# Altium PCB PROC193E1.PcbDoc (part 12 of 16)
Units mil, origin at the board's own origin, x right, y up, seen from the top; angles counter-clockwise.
Board outline 7700 x 2300 mil, 6 copper layers (Top Layer, GND 1, SIG 1, PWR, GND 2, Bottom Layer), stack 60.98 mil thick; 946 components, 667 nets, 9401 pads, 1730 vias.
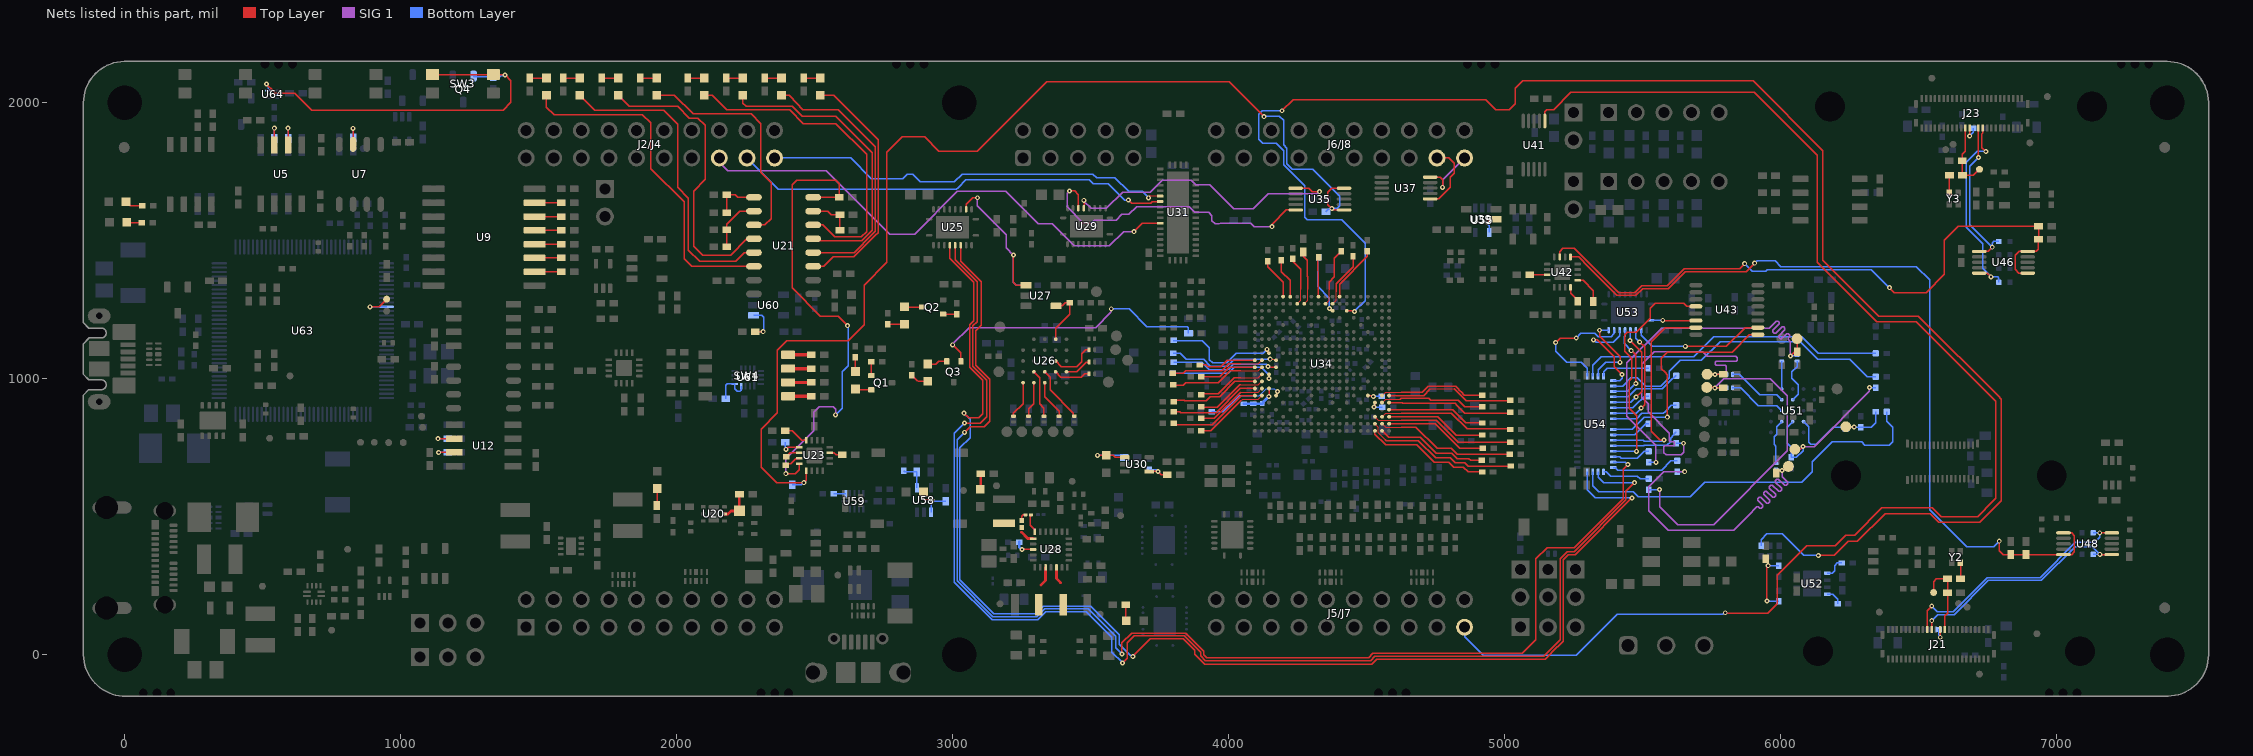
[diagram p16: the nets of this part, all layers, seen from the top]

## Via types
v1: diameter 18, hole 8, Top Layer to Bottom Layer, tented both sides, 1710 vias
v2: diameter 18, hole 8, Top Layer to Bottom Layer, tented top, 12 vias
v3: diameter 23.62, hole 11.81, Top Layer to Bottom Layer, tented both sides, 8 vias

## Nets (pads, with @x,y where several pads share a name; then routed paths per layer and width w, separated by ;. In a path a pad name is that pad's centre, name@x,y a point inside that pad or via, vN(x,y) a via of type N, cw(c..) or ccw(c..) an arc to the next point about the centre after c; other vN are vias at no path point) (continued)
I2C1_SDA/GPIO136: J5/J7.50 U41.6 | length 5047.8
  Top Layer w5.3: U41.6@5145.29,1934.2 5145.29,1967.62 5152.68,1975.01 5176.73,1975.01 5239.85,2038.13 5903.11,2038.13 6131.62,1809.62 6131.62,1422.45 6347.18,1206.9 6490.27,1206.9 6778.91,918.26 6778.91,566.97 6767.79,555.85 6712.73,500.78 6580.92,500.78 6549.26,532.44 6536.12,532.44 6366.44,532.44 6267.06,433.06 6235.77,433.06 6198.08,395.37 6094.25,395.37 6088.32,389.44 5986.96,288.08 5986.96,184.37 5953.38,150.79 5800.23,150.79 v1(5798.69,152.33)
  Bottom Layer w5.3: J5/J7.50@4854.17,100 4855.77,98.4 4855.77,64.64 4921.15,-0.73 5259.43,-0.73 5395.83,135.67 5396.03,135.67 5406.57,146.21 5789.23,146.21 5795.36,152.33 v1(5798.69,152.33)
I2C_EX1_ADDR: R188.2 U42.16 | length 60.2
  Top Layer w5.3: U42.16@5238.05,1331.1 5238.05,1310.38 5263.64,1284.79 R188.2@5263.64,1281.48
I2C_EX1_INTN: R184.2 U42.11 | length 62.6
  Top Layer w5.3: R184.2@5090.84,1376.37 U42.11@5153.4,1376.37
I2C_EX1_RSTN: R191.2 U42.1 | length 111.8
  Top Layer w5.3: U42.1@5263.64,1356.69 5283.4,1356.69 5321.3,1318.78 R191.2@5321.3,1280.35
I2C_EX2_ADDR: R63.1 U23.16 | length 90.5
  Top Layer w5.3: R63.1@2392.66,811.04 2418.1,811.04 2451.88,777.27 U23.16@2469.17,777.27
I2C_EX2_INTN: R77.2 U23.11 | length 48.9
  Top Layer w5.3: U23.11@2553.81,731.99 2554.09,731.71 2569.55,731.71 2576.99,724.27 R77.2@2599.51,724.27
I2C_EX2_RSTN: R364.2 U23.1 | length 77.9
  Top Layer w5.3: v1(2395.21,744.52) 2397.51,744.52 2404.66,751.68 U23.1@2443.57,751.68
  Bottom Layer w5.3: R364.2@2392.66,770 2392.66,747.07 v1(2395.21,744.52)
ICSS1_INH: J21.26 R239.2 | length 58.8
  Top Layer w5.3: v1(6577.74,63.37) 6578.04,63.66 J21.26@6578.04,91.39
  Bottom Layer w5.3: R239.2@6572.06,91.67 6572.06,72.49 6577.74,66.81 v1(6577.74,63.37)
ICSS2_INH: J23.26 R233.2 | length 62.3
  Top Layer w5.3: v1(6684.43,1879.92) J23.26@6684.43,1908.44
  Bottom Layer w5.3: v1(6684.43,1879.92) 6697.48,1892.97 R233.2@6697.48,1908.33
INT1_PB: Q4.2 R378.1 SW3.2 SW3.4 U64.3 | length 1453.2
  Top Layer w5.3: v1(513.14,2068) 540.03,2041.1 545.91,2035.23 615.14,2035.23 677.45,1972.91 1219.96,1972.91 1235.6,1972.91 1370.64,1972.91 1399.03,2001.3 1399.03,2079.77 v1(1377.8,2101) 1336.52,2101 SW3.4@1335.24,2102.28 SW3.2@1114.76,2102.28
  Bottom Layer w5.3: v1(513.14,2068) 519.68,2061.46 U64.3@519.68,2043.98 ; Q4.2@1263.53,2096.74 1265.15,2095.12 R378.1@1335.24,2095.12 1358.2,2095.12 1361.65,2098.57 1375.37,2098.57 v1(1377.8,2101)
LED_A0: R55.2 R56.2 U21.9 | length 166.8
  Top Layer w5.3: R55.2@2181.39,1602.28 R56.2@2181.39,1666.96 2211.84,1666.96 2221.37,1657.42 U21.9@2279.55,1657.42
LED_A1: R53.2 R54.2 U21.10 | length 198.7
  Top Layer w5.3: R53.2@2181.39,1478.99 R54.2@2181.39,1539.3 2181.39,1559.83 2228.98,1607.42 U21.10@2279.55,1607.42
LED_A2: R75.2 R76.2 U21.7 | length 157.7
  Top Layer w5.3: U21.7@2494.12,1607.42 2546.84,1607.42 2560.28,1593.98 R76.2@2591.22,1593.98 R75.2@2591.22,1538.98
LED_ANODE0: D11.2 R67.1 | length 60
  Top Layer w5.3: R67.1@2459.29,2089.8 D11.2@2519.29,2089.8
LED_ANODE1: D10.2 R62.1 | length 60
  Top Layer w5.3: R62.1@2319.29,2089.8 D10.2@2379.29,2089.8
LED_ANODE2: D9.2 R58.1 | length 60
  Top Layer w5.3: R58.1@2179.29,2089.8 D9.2@2239.29,2089.8
LED_ANODE3: D8.2 R52.1 | length 60
  Top Layer w5.3: R52.1@2039.29,2089.8 D8.2@2099.29,2089.8
LED_ANODE4: D6.2 R42.1 | length 60
  Top Layer w5.3: R42.1@1867.87,2089.8 D6.2@1927.87,2089.8
LED_ANODE5: D5.2 R41.1 | length 60
  Top Layer w5.3: R41.1@1727.87,2089.8 D5.2@1787.87,2089.8
LED_ANODE6: D4.2 R38.1 | length 60
  Top Layer w5.3: R38.1@1587.87,2089.8 D4.2@1647.87,2089.8
LED_ANODE7: D3.2 R26.1 | length 60
  Top Layer w5.3: R26.1@1467.87,2089.8 D3.2@1527.87,2089.8
LED_DRAIN0: D11.1 U21.3 | length 898.8
  Top Layer w5.3: U21.3@2494.12,1407.42 2532.47,1407.42 2566.86,1441.82 2641.63,1441.82 2719.59,1519.78 2729.32,1529.5 2729.32,1548.83 2729.32,1805.31 2729.32,1811.99 2729.32,1819.74 2729.32,1834.05 2729.32,1865.9 2568.4,2026.81 D11.1@2519.29,2026.81
LED_DRAIN1: D10.1 U21.4 | length 981
  Top Layer w5.3: D10.1@2379.29,2026.81 2407.66,2026.81 2410.77,2023.71 2456.86,1974.27 2585.73,1974.27 2718.72,1841.29 2718.72,1553.22 2718.72,1533.89 2708.99,1524.17 2642.25,1457.42 U21.4@2494.12,1457.42
LED_DRAIN2: D9.1 U21.5 | length 1085.8
  Top Layer w5.3: D9.1@2239.29,2026.81 2239.29,1998.55 2251.11,1986.73 2418.49,1986.73 2453.8,1951.42 2576.58,1951.42 2708.11,1819.89 2708.11,1557.62 2708.11,1538.28 2669.59,1499.76 2501.78,1499.76 U21.5@2494.12,1507.42
LED_DRAIN3: D8.1 U21.6 | length 1176.9
  Top Layer w5.3: D8.1@2099.29,2026.81 2129.12,2026.81 2181.66,1974.27 2408.67,1974.27 2458.21,1924.73 2576.27,1924.73 2687.79,1813.21 2687.79,1602.13 2687.79,1585.95 2687.79,1532.95 2668.7,1513.86 2572.48,1513.86 2528.92,1557.42 U21.6@2494.12,1557.42
LED_DRAIN4: D6.1 U21.11 | length 850.9
  Top Layer w5.3: D6.1@1927.87,2026.81 1991.48,2026.81 2058.87,1959.42 2269.55,1959.42 2304.25,1924.73 2304.25,1748.99 2342.2,1711.03 2342.2,1580.33 2319.29,1557.42 U21.11@2279.55,1557.42
LED_DRAIN5: D5.1 U21.12 | length 1072
  Top Layer w5.3: D5.1@1787.87,2026.81 1827.95,1986.73 2003.75,1986.73 2045.7,1944.78 2076.59,1944.78 2103.23,1918.14 2103.23,1722.11 2061.23,1680.11 2061.23,1480.09 2093.24,1448.08 2194.74,1448.08 2254.08,1507.42 U21.12@2279.55,1507.42
LED_DRAIN6: D4.1 U21.13 | length 1138.5
  Top Layer w5.3: D4.1@1647.87,2026.81 1702.19,1972.5 1953.33,1972.5 2003.75,1922.08 2003.75,1693.24 2042.23,1654.76 2042.23,1466.03 2082.64,1425.62 2212.84,1425.62 2244.64,1457.42 U21.13@2279.55,1457.42
LED_DRAIN7: D3.1 U21.14 | length 1250.8
  Top Layer w5.3: D3.1@1527.87,2026.81 1527.87,1984.63 1555.24,1957.27 1875.6,1957.27 1906,1926.87 1906,1761.39 2026.48,1640.91 2026.48,1434.43 2053.49,1407.42 U21.14@2279.55,1407.42
LED_DRIVER_EN: R74.2 U21.8 U23.4 | length 1749.9
  Top Layer w5.3: v1(2395.05,656.33) 2428.94,656.33 2443.57,670.97 U23.4@2443.57,692.62 ; U21.8@2494.12,1657.42 R74.2@2588.21,1657.42 2588.21,1706.9 2575.47,1719.64 2433.89,1719.64 2418.09,1703.84 2418.09,1329.43 2520.44,1227.09 2584.11,1227.09 v1(2618.69,1192.5)
  SIG 1 w5.3: v1(2395.05,656.33) 2395.05,710.02 2496.99,811.96 2496.99,877.99 2516.93,897.93 2567.07,897.93 2575.47,889.53 v1(2575.47,869.52)
  Bottom Layer w5.3: v1(2575.47,869.52) 2600.11,894.16 2600.11,1026.72 2603.43,1030.04 2609.46,1036.07 2609.46,1036.15 2620.4,1047.08 2620.4,1190.79 v1(2618.69,1192.5)
LIN1_RXD/PR1_PRU1_GPIO0: J2/J4.33 U31.11 | length 1899.9
  Top Layer w5.3: v1(3656,1533) 3686.61,1563.61 U31.11@3751.12,1563.61
  SIG 1 w4.75: J2/J4.33@2154.17,1800 2154.17,1785.28 2185.12,1754.33 2541.05,1754.33 2771.05,1524.33 2861.86,1524.33 3016.69,1679.16 3192.46,1679.16 3309.79,1561.84 3359.71,1561.84 3440.17,1481.38 3567.23,1481.38 3618.85,1533 v1(3656,1533)
M_EQEP0_A: U43.6 U53.1 | length 162.4
  Top Layer w5.3: v1(5572.32,1211.87) 5573.09,1211.11 5603.41,1211.11 5652.29,1211.11 U43.6@5692.24,1211.11
  Bottom Layer w5.3: U53.1@5530.13,1211.87 v1(5572.32,1211.87)
M_EQEP0_B: U43.10 U53.3 | length 485.6
  Top Layer w5.3: v1(5654.03,1117.71) 5802.93,1117.71 5870.74,1185.52 U43.10@5916.65,1185.52
  Bottom Layer w5.3: U53.3@5494.7,1176.44 5494.7,1157.3 5534.28,1117.71 v1(5654.03,1117.71)
M_EQEP0_INDEX: U53.4 U54.28 | length 409.1
  Top Layer w5.3: v1(5488.74,1133) 5506.27,1115.47 5506.27,1101.02 ; v1(5494.06,894.07) 5506.27,906.28 5506.27,942.93 ; 5506.28,942.94 5506.28,977.4 5506.28,1101.01
  Bottom Layer w5.3: U54.28@5393.04,875.4 5475.39,875.4 v1(5494.06,894.07) ; U53.4@5475.01,1176.44 5475.01,1146.73 v1(5488.74,1133)
M_EQEP0_STROBE: U53.5 U54.26 | length 359.6
  Top Layer w5.3: v1(5453.42,1138.88) 5495.68,1096.62 5495.68,953.98 v1(5476.16,934.46)
  Bottom Layer w5.3: U54.26@5393.04,914.77 5456.48,914.77 v1(5476.16,934.46) ; v1(5453.42,1138.88) 5455.33,1140.79 U53.5@5455.33,1176.44
M_EQEP1_A: U53.6 U54.24 | length 306.9
  Top Layer w5.3: v1(5458,1102) 5459.31,1102 5474.54,1086.78 v1(5474.54,982.98)
  Bottom Layer w5.3: U54.24@5393.04,954.14 5445.69,954.14 v1(5474.54,982.98) ; U53.6@5435.64,1176.44 5435.64,1156.68 5431.88,1152.92 5431.88,1128.12 v1(5458,1102)
M_EQEP1_B: U53.7 U54.22 | length 352.9
  Top Layer w5.3: v1(5321.75,1141.1) 5335.73,1141.1 5396.27,1080.56 5396.27,1043.54 v1(5424.23,1015.58)
  Bottom Layer w5.3: v1(5321.75,1141.1) 5323.07,1141.1 5331.21,1132.97 5392.25,1132.97 5415.96,1156.68 U53.7@5415.96,1176.44 ; U54.22@5393.04,993.51 5416.87,993.51 5425,1001.64 5425,1014.81 v1(5424.23,1015.58)
M_EQEP1_INDEX: U53.8 U54.18 | length 448
  Top Layer w5.3: v1(5184.36,1131.22) 5200.79,1147.65 v1(5258.87,1147.65)
  Bottom Layer w5.3: v1(5184.36,1131.22) 5184.22,1131.07 5184.22,1099.61 5223.62,1060.21 5276.26,1060.21 5298.55,1037.92 U54.18@5298.55,1009.26 ; v1(5258.87,1147.65) 5276.01,1164.78 5326.2,1164.78 5338.03,1152.95 5385.26,1152.95 5395.48,1163.17 5395.48,1175.65 U53.8@5396.27,1176.44
M_EQEP1_STROBE: U53.9 U54.20 | length 294.3
  Top Layer w5.3: v1(5343.46,1175.91) 5343.46,1153.43 5417.64,1079.24 v1(5417.64,1059.69)
  Bottom Layer w5.3: U54.20@5337.92,1009.26 5337.92,1032.14 5365.47,1059.69 v1(5417.64,1059.69) ; v1(5343.46,1175.91) 5343.73,1176.17 5376.32,1176.17 U53.9@5376.59,1176.44
M_FSIRX0_CLK: U43.4 U54.35 | length 862.9
  Top Layer w5.3: v1(5477.58,737.18) 5477.58,866.42 5451.52,892.48 5451.52,992.96 5460.66,1002.1 5460.66,1073.04 5450.35,1083.35 5450.27,1083.35 5439.35,1094.28 5439.35,1094.35 5434.09,1099.61 5434.09,1159.32 5443.26,1168.48 5475.67,1168.48 5527.45,1220.26 5527.45,1255.75 5544.66,1272.96 5648.16,1272.96 5658.83,1262.29 U43.4@5692.24,1262.29
  Bottom Layer w5.3: U54.35@5393.04,737.61 5477.15,737.61 v1(5477.58,737.18)
M_FSIRX0_DATA0/EQEP0_A: U43.7 U54.33 | length 752.1
  Top Layer w5.3: v1(5576.67,777.97) 5576.53,778.11 5563.44,778.11 5530.99,810.56 5530.99,1134.4 5582.12,1185.52 U43.7@5692.24,1185.52
  Bottom Layer w5.3: U54.33@5393.04,776.98 5501.34,776.98 5504.47,773.85 5569.11,773.85 5573.24,777.97 v1(5576.67,777.97)
M_FSIRX0_DATA1/EQEP0_B: U43.9 U54.31 | length 822.4
  Top Layer w5.3: v1(5588.66,860.76) 5588.66,1015.25 5580.86,1023.05 5580.66,1023.05 5566.83,1036.88 5566.83,1074.91 5588.91,1097 5823.66,1097 5886.59,1159.93 U43.9@5916.65,1159.93
  Bottom Layer w5.3: U54.31@5393.04,816.35 5461.28,816.35 5505.69,860.76 v1(5588.66,860.76)
M_FSITX0_CLK: U25.5 U54.42 | length 4707.3
  Top Layer w5.3: U25.5@2989.13,1484.11 2989.13,1435.88 3075.76,1349.24 3075.76,1210.01 3061.46,1195.7 3061.46,1041.2 3108.47,994.19 3108.47,873.06 3094.09,858.68 3057.22,858.68 v1(3040.35,875.54) ; v1(3652.17,-5.73) 3715.84,57.94 3834.67,57.94 3876.54,16.07 3876.54,2.12 3912.04,-33.39 4518.61,-33.39 4536.26,-15.74 5146.04,-15.74 5190.83,29.05 5191.04,29.05 5211.87,49.88 5211.87,344.39 5230.79,363.32 5255.13,363.32 v1(5460.35,568.53)
  Bottom Layer w5.3: v1(3040.35,875.54) 3062.6,853.29 3062.6,786.29 3025.8,749.49 3025.8,271.84 3148.94,148.7 3149.72,147.92 3150.83,147.92 3299.72,147.92 3328.54,176.75 3499.05,176.75 3603.66,72.14 3603.66,38.71 3643.45,-1.08 3644.09,-1.08 3648.74,-5.73 v1(3652.17,-5.73) ; U54.42@5298.55,662.8 5298.55,598.52 5328.54,568.53 v1(5460.35,568.53)
M_FSITX0_DATA0: U25.6 U54.40 | length 4737.9
  Top Layer w5.3: U25.6@3008.81,1484.11 3008.81,1431.19 3087.68,1352.32 3087.68,1206.93 3072.06,1191.31 3072.06,1045.59 3122.46,995.18 3122.46,862.98 3098.85,839.37 v1(3042.19,839.37) ; v1@3615.26,-29.15 3631.97,-12.44 3631.97,42.77 3657.44,68.24 3838.93,68.24 3898.37,8.81 3898.37,-3.75 3915.42,-20.8 4513.57,-20.8 4528.93,-5.44 5141.77,-5.44 5186.56,39.35 5186.77,39.35 5201.57,54.14 5201.57,348.66 5226.53,373.61 5250.87,373.61 5439,561.75 5439,593.09 v1(5469.57,623.65)
  Bottom Layer w5.3: v1(3042.19,839.37) 3004.97,802.14 3004.97,263.54 3140.41,128.1 3141.32,127.19 3142.43,127.19 3308.12,127.19 3337.07,156.15 3484.23,156.15 3576.01,64.37 3576.01,9.83 v1(3615.13,-29.28) ; U54.40@5337.92,662.8 5337.92,643.82 5350.21,631.54 5358.09,623.65 v1(5469.57,623.65)
M_FSITX0_DATA1: U25.7 U54.37 | length 4624.1
  Top Layer w5.3: U25.7@3028.5,1484.11 3028.5,1426.49 3102.68,1352.32 3102.68,1193.93 3082.66,1173.91 3082.66,1049.98 3134.62,998.02 3134.62,846.84 3114.28,826.5 3062.97,826.5 v1(3042.46,805.99) ; v1(3613,3) 3613,42.91 3648.63,78.54 3843.2,78.54 3908.67,13.07 3908.67,0.51 3919.59,-10.41 4506.32,-10.41 4521.59,4.86 5063.75,4.86 5112.72,53.82 5112.72,348.07 5153.19,388.54 5251.23,388.54 5428.45,565.76 5428.45,671.9 v1(5445.58,689.03)
  Bottom Layer w5.3: v1(3042.46,805.99) 3015.27,778.8 3015.27,267.81 3144.68,138.4 3145.58,137.49 3146.7,137.49 3303.85,137.49 3332.81,166.45 3491.06,166.45 3591.05,66.46 3591.05,24.95 v1(3613,3) ; U54.37@5393.04,698.23 5436.12,698.23 5445.33,689.03 v1(5445.58,689.03)
M_OSPI1_CLK: R242.1 R245.1 U54.41 | length 1383.5
  Bottom Layer w5.3: U54.41@5318.24,662.8 5318.24,612.8 5340.05,590.99 5465.5,590.99 5483.01,573.48 5671.74,573.48 5723.56,625.31 6076.31,625.31 6113.45,662.45 6113.45,698.63 6186.47,771.64 6293.36,771.64 6305,760 6393.17,760 6405,771.83 6405,824.18 6383.34,845.84 6383.34,880.25 R242.1@6383.42,880.32
M_OSPI1_CSN0: R243.1 R248.1 U54.23 | length 1107.9
  Bottom Layer w5.3: U54.23@5393.04,973.83 5427.38,973.83 5456.76,1003.2 5480.69,1003.2 5493.19,990.71 5493.19,990.63 5509.99,973.83 5565.69,973.83 5596.28,1004.42 5596.28,1026.91 5636.37,1067 5712,1067 5780,1135 6070.43,1135 6133.77,1071.66 6249.34,1071.66 6313.74,1007.26 R248.1@6343.71,1007.26
M_OSPI1_D0: R286.1 R291.1 U54.39 | length 173.8
  Bottom Layer w5.3: U54.39@5357.61,662.8 5368.25,662.8 5383.78,647.27 5480.73,647.27 5489.89,638.11 R291.1@5521.14,638.11
M_OSPI1_D1: R276.1 R282.1 U54.38 | length 250.5
  Bottom Layer w5.3: U54.38@5393.04,678.55 5399.93,678.55 5410.01,668.47 5567.94,668.47 5602.05,702.58 R282.1@5625.21,702.58
M_OSPI1_D2: R289.1 R294.1 U54.36 | length 140.9
  Bottom Layer w5.3: U54.36@5393.04,717.92 5416.34,717.92 5422.58,711.68 5479.7,711.68 5504.67,736.65 R294.1@5520.97,736.65
M_OSPI1_D3: R277.1 R283.1 U54.34 | length 257.7
  Bottom Layer w5.3: U54.34@5393.04,757.29 5502.82,757.29 5504.52,758.99 5535.17,758.99 5535.71,758.45 5587.42,758.45 5600.91,771.93 5600.91,785.32 5612.11,796.53 5612.11,798.5 5619.3,805.69 R283.1@5621.27,805.69
M_OSPI1_D4: R287.1 R292.1 U54.32 | length 145
  Bottom Layer w5.3: U54.32@5393.04,796.66 5470.71,796.66 5472.34,798.29 5511.44,837.39 R292.1@5521.14,837.39
M_OSPI1_D5: R278.1 R284.1 U54.29 | length 248.2
  Bottom Layer w5.3: U54.29@5393.04,855.72 5460.66,855.72 5477.69,855.72 5496.36,874.39 5574.43,874.39 5581.02,880.98 5603.95,903.91 R284.1@5621.27,903.91
M_OSPI1_D6: R290.1 R295.1 U54.27 | length 145.5
  Bottom Layer w5.3: U54.27@5393.04,895.09 5464.4,895.09 5484.25,914.93 5495.69,926.37 5506.73,937.41 R295.1@5520.97,937.41
M_OSPI1_D7: R279.1 R285.1 U54.25 | length 260.2
  Bottom Layer w5.3: U54.25@5393.04,934.46 5447.39,934.46 5476.16,963.23 5570.08,963.23 5573.59,966.74 5573.76,966.74 5598.35,991.33 5618.64,1011.62 R285.1@5621.27,1011.62
M_OSPI1_DQS: R288.1 R293.1 U54.21 | length 184.4
  Bottom Layer w5.3: U54.21@5357.61,1009.26 5358.24,1009.89 5358.24,1024.85 5371.96,1038.57 R293.1@5521.14,1038.57
M_OSPI1_ECC_FAIL: R244.1 R249.1 U54.19 | length 1132.5
  Bottom Layer w5.3: U54.19@5318.24,1009.26 5318.24,1048.44 5349.74,1079.95 5684.52,1079.95 5756.58,1152 6075.44,1152 6135.62,1091.82 6343.65,1091.82 R249.1@6343.71,1091.76
MCAN0_RX: U29.17 U35.10 | length 1100.3
  Top Layer w5.3: v1(3422.56,1680.77) 3442.17,1680.77 3455.31,1667.64 3455.31,1651.47 3455.13,1651.29 U29.17@3455.13,1618.16 ; v1(4156.69,1551.25) 4156.69,1560.83 4207.5,1611.64 U35.10@4242.38,1611.64
  SIG 1 w4.75: v1(3422.56,1680.77) 3413.77,1671.98 3413.77,1623.24 3473.42,1563.59 3477.96,1563.59 3501.66,1563.59 3513.07,1575 3592.4,1575 3612.78,1595.38 3637.27,1595.38 3665.77,1623.88 3856.16,1623.88 3877.06,1602.98 3926.57,1602.98 3938.82,1590.73 3938.82,1573.16 3950.09,1561.89 3966.04,1561.89 3968.52,1564.37 4079.58,1564.37 4092.69,1551.25 v1(4156.69,1551.25)
MCAN0_RX/PR1_PRU1_GPIO2: J2/J4.31 U31.6 | length 1496.5
  Top Layer w5.3: v1@3709.11,1655.67 3715.88,1662.33 U31.6@3751.12,1662.03
  Bottom Layer w5.3: J2/J4.31@2354.17,1800 2629.93,1800 2704.71,1725.21 2818.55,1725.21 2835.36,1742.02 2854.31,1742.02 2882.8,1713.53 3005.65,1713.53 3033.62,1741.49 3507.97,1741.49 3520.88,1728.58 3521.61,1728.58 3522.04,1728.15 3587.23,1728.15 3636.6,1678.78 3685.92,1678.78 v1(3709.07,1655.63)
MCAN0_STB: R265.2 U34.C14 | length 5947
  Top Layer w5.3: v1(4192.41,1971.23) 4233.07,2011.88 4930.19,2011.88 4967.77,1974.31 5015.4,1974.31 5037.44,1996.35 5037.44,2052.97 5064.47,2080 5899.41,2080 6152.82,1826.59 6152.82,1430.39 6355.71,1227.5 6498.81,1227.5 6502.46,1223.84 6788.39,937.91 6799.51,926.79 6799.51,558.43 6721.26,480.18 6572.38,480.18 6540.73,511.84 6377.84,511.84 6276.64,410.64 6243.5,410.64 6193.01,360.14 v1(6135.75,360.14) ; U34.C14@4427.16,1246.42 4429.92,1246.42 4452.75,1246.42 v1(4455.07,1244.11)
  Bottom Layer w5.3: v1(4192.41,1971.23) 4120.49,1971.23 4108.48,1959.21 4108.48,1868.03 4122.43,1854.07 4171.58,1854.07 4199.8,1825.85 4199.8,1774.92 4202.54,1772.19 4202.54,1771.76 4274.46,1699.84 4274.46,1586.11 4284.3,1576.27 4409.3,1576.27 4481.01,1504.55 4494.37,1491.19 4494.37,1283.41 v1(4455.07,1244.11) ; R265.2@5928.76,395.65 5928.76,417.35 5949.17,437.76 6005.31,437.76 6082.93,360.14 v1(6135.75,360.14)
MCAN0_TX: U29.16 U35.6 | length 1098
  Top Layer w5.3: v1(3474.72,1646.56) 3476.12,1645.16 3476.12,1629.49 3475.61,1628.97 3475.61,1618.95 U29.16@3474.81,1618.16 ; U35.6@4242.38,1690.38 4242.46,1690.3 4290.45,1690.3 4302.7,1678.05 v1(4328.28,1678.05)
  SIG 1 w4.75: v1(3474.72,1646.56) 3474.72,1643.62 3501.24,1617.1 3555.92,1617.1 3615.13,1676.3 3716.02,1676.3 3758.95,1719.23 3863.77,1719.23 3880.07,1702.93 3931.24,1702.93 3973.53,1660.64 4017.18,1617 4089.05,1617 4142.75,1670.69 4318.87,1670.69 4326.23,1678.05 v1(4328.28,1678.05)
MCAN0_TX/PR1_PRU1_GPIO1: J2/J4.32 U31.7 | length 1596.1
  Top Layer w5.3: v1(3635.93,1647.79) 3647.61,1636.1 3717.16,1636.1 3723.4,1642.35 U31.7@3751.12,1642.35
  Bottom Layer w5.3: J2/J4.32@2254.17,1800 2367.93,1686.24 3012.59,1686.24 3019.02,1692.67 3047.24,1720.89 3494.45,1720.89 3508.39,1706.95 3563.05,1706.95 3622.21,1647.79 v1(3635.93,1647.79)
MCAN1_RX/PR1_PRU0_GPIO9: J6/J8.71 U37.10 | length 215.6
  Top Layer w5.3: U37.10@4729.47,1730.45 4751.9,1730.45 4765.89,1730.45 4774.52,1721.81 v1(4774.52,1693.9)
  SIG 1 w4.75: v1(4774.52,1693.9) 4774.52,1720.35 J6/J8.71@4854.17,1800
MCAN1_TX/PR1_PRU0_GPIO7: J6/J8.72 U37.6 | length 252.4
  Top Layer w5.3: U37.6@4729.47,1651.71 4759.95,1651.71 4801.84,1693.6 4801.84,1729.85 4816.13,1744.15 4816.13,1780.12 4796.25,1800 J6/J8.72@4754.17,1800
MCAN_MUX_SEL: R316.2 R363.1 U23.5 U35.1 U35.5 | length 4043.9
  Top Layer w5.3: U23.5@2469.17,667.03 2468.67,666.53 2468.67,632.91 2460.3,624.54 v1(2460.3,623.46) 2362.94,623.46 2306.29,680.11 2306.29,817.93 2364.65,876.29 2364.65,1103.84 2399.15,1138.34 2620.73,1138.34 2678.86,1196.48 2678.86,1339.38 2761.11,1421.63 2761.11,1516.33 2761.11,1820.88 2816.33,1876.1 2898.74,1876.1 2949.75,1825.09 2986.82,1825.09 3089.38,1825.09 3099.24,1834.95 3339.84,2075.55 4001.98,2075.55 v1(4128.02,1949.51) ; U35.1@4417.57,1611.64 4378.77,1611.64 v1(4373.26,1617.15) 4359.39,1631.02 4359.39,1675.97 4373.8,1690.38 U35.5@4417.57,1690.38
  Bottom Layer w5.3: R363.1@2417.61,616.18 2450.84,616.18 2458.12,623.46 v1(2460.3,623.46) ; v1(4128.02,1949.51) 4129.4,1950.89 4183.19,1950.89 4198.2,1935.88 4198.2,1848.02 4210.1,1836.12 4210.1,1779.19 4230.33,1758.96 4304.45,1758.96 4401.29,1662.12 4401.29,1626.37 4392.08,1617.15 4369.83,1617.15 4366.6,1613.92 4361.07,1613.92 R316.2@4351.91,1604.76
MDIO/MDC_MUX_SEL1: R216.1 R217.2 U42.5 U48.1 U48.5 | length 3008.1
  Top Layer w5.3: U42.5@5238.05,1441.33 5268.3,1441.33 5285.97,1423.66 5285.97,1421.48 5405.46,1302 5474.92,1302 5499.77,1326.85 5592.66,1326.85 5654.18,1388.36 5874.72,1388.36 v1(5905.3,1418.94) ; v1(6791.42,411.53) 6791.42,377.57 6805.61,363.39 R216.1@6833.24,363.39 R217.2@6888.43,363.39 6918.63,363.39 ; 6918.63,363.15 U48.5@7024.14,363.15 7054.19,363.15 7063.99,372.95 7063.99,431.43 7053.53,441.89 U48.1@7024.14,441.89
  Bottom Layer w5.3: v1(5905.3,1418.94) 5906.7,1418.94 5914.76,1427 5980.26,1427 6000.39,1406.87 6491.34,1406.87 6539.89,1358.31 6539.89,525.33 6673.28,391.94 6771.83,391.94 v1(6791.42,411.53)
MDIO/MDC_MUX_SEL2: R218.1 R219.2 U42.7 U46.1 U46.5 | length 2370.4
  Top Layer w5.3: U42.7@5198.68,1441.33 5198.68,1460.68 5210.21,1472.21 5252.07,1472.21 5411.98,1312.3 5470.65,1312.3 5495.49,1337.15 5588.39,1337.15 5649.91,1398.66 5850.8,1398.66 v1(5869.3,1417.16) ; v1(6393.82,1330.03) 6411.77,1312.08 6526.35,1312.08 6592.5,1378.23 6592.5,1502.83 6642.95,1553.28 R219.2@6934.03,1553.28 6934.03,1505.36 R218.1@6933.64,1504.96 6933.64,1470.28 6924.95,1461.59 U46.5@6894.37,1461.59 6863.05,1461.59 6848.83,1447.37 6848.83,1396.63 6862.62,1382.85 U46.1@6894.37,1382.85
  Bottom Layer w5.3: v1(5869.3,1417.16) 5897.03,1389.44 5945.29,1389.44 5951.73,1395.88 6327.97,1395.88 v1(6393.82,1330.03)
MDIO_CLOCK_ETH1: J21.20 R226.1 U48.10 | length 903.8
  Top Layer w5.3: J21.20@6530.79,91.39 6530.79,160.36 v1(6546.91,176.47) ; v1(7155.63,441.85) 7155.67,441.89 U48.10@7199.34,441.89
  Bottom Layer w5.3: v1(6546.91,176.47) 6567.04,156.34 6624.41,156.34 6747.77,279.7 6939.3,279.7 7067.58,407.98 7137.54,407.98 7155.63,426.07 v1(7155.63,441.85) 7155.44,442.03 R226.1@7131.92,442.03
MDIO_CLOCK_ETH2: J23.20 R227.1 U46.10 | length 725.6
  Top Layer w5.3: U46.10@6719.18,1382.85 6748.57,1382.85 v1(6761.95,1369.47) ; J23.20@6731.68,1908.44 6731.68,1890.55 6728.78,1887.65 6728.78,1837.92 6740.7,1826 v1(6742.9,1823.8)
  Bottom Layer w5.3: v1(6742.9,1823.8) 6711.04,1823.8 6671.07,1783.83 6671.07,1549.03 6731.34,1488.76 6731.34,1400.07 v1(6761.95,1369.47) 6785.32,1369.47 6789.85,1364.94 R227.1@6789.85,1349.46
MDIO_DATA_ETH1: J21.22 R225.1 U48.6 | length 832.3
  Top Layer w5.3: J21.22@6546.54,91.39 v1@6546.54,123.39 ; v1(7155.69,364.01) 7156.55,363.15 U48.6@7199.34,363.15
  Top Layer w8: v1@6546.54,123.39 v1(6546.88,123.73)
  Bottom Layer w5.3: v1(6546.88,123.73) 6568.45,145.3 6627.93,145.3 6752.03,269.4 6943.56,269.4 7066.1,391.94 7128.4,391.94 7155.69,364.65 v1(7155.69,364.01) 7155.31,363.62 R225.1@7131.92,363.62
MDIO_DATA_ETH2: J23.22 R229.1 U46.6 | length 573.1
  Top Layer w5.3: v1(6715.93,1801.72) J23.22@6715.93,1908.44 ; U46.6@6719.18,1461.59 6751.47,1461.59 6766.07,1476.19 v1(6766.07,1476.9)
  Bottom Layer w5.3: v1(6715.93,1801.72) 6684.43,1770.22 6684.43,1558.54 v1(6766.07,1476.9) 6766.07,1491.82 6771.79,1497.54 R229.1@6789.85,1497.54
NetC65_1: C65.1 R94.2 | length 30.3
  Top Layer w5.3: C65.1@3250.5,486.66 3250.5,502.25 3255.14,506.89 R94.2@3263.33,506.89
NetC65_2: C65.2 L3.1 U28.8 | length 52.4
  Top Layer w10: 3248.27,444.31 3271.66,420.91 U28.8@3290.99,420.91
NetC114_1: C114.1 R261.1 R262.1 | length 246.2
  Top Layer w5.3: C114.1@5944.74,347.74 5952.08,347.74 5952.08,325.1 v1(5954.4,322.78) 5949.57,317.94 v1(5949.57,195.12)
  Bottom Layer w5.3: v1(5949.57,195.12) 5950.01,194.68 5991.77,194.68 R261.1@5993.11,193.34 ; v1(5954.4,322.78) 5955.1,322.08 R262.1@5993.11,322.08
NetC227_1: C227.1 R320.1 R321.1 U34.P3 | length 130.1
  Top Layer w5.3: v1(4144.82,935.57) 4145.67,936.42 U34.P3@4145.67,964.93
  Bottom Layer w10: R321.1@4053.85,909.83 R320.1@4089.02,909.83 C227.1@4121.3,909.83 ; C227.1@4123.8,911.3 4124.76,912.26 4124.76,915.52 v1(4144.82,935.57)
NetD1_2: D1.2 R1.1 | length 54.4
  Top Layer w5.3: D1.2@7.47,1567.07 8.85,1565.68 R1.1@61.29,1565.68
NetD7_2: D7.2 R44.1 | length 61.8
  Top Layer w5.3: R44.1@1927.95,540.93 1929,541.99 D7.2@1929,602.25
NetD12_2: D12.2 R350.1 U58.1 | length 155.2
  Top Layer w5.3: D12.2@2893.66,590.14 2893.66,566.76 2898.91,561.51 v1(2924.11,561.51)
  Bottom Layer w5.3: U58.1@2921.22,516.32 2922.66,517.77 2922.66,560.06 v1(2924.11,561.51) 2929.27,556.35 R350.1@2974.77,556.35
NetD13_1: D13.1 Q3.2 | length 72.2
  Top Layer w5.3: D13.1@2909.63,1053.56 2939.1,1053.56 2948.43,1062.88 Q3.2@2977.96,1062.88
NetD13_2: D13.2 R84.1 | length 67.3
  Top Layer w5.3: R84.1@2851.59,1012.99 2871.35,993.23 2874.01,990.56 D13.2@2909.63,990.56
NetD14_2: D14.2 R87.1 | length 56.5
  Top Layer w10: D14.2@3099.79,600.36 3101.17,601.74 R87.1@3101.17,656.33
NetD15_2: D15.2 R334.1 U30.1 | length 201.7
  Top Layer w5.3: v1(3524.33,722.69) 3524.49,722.53 D15.2@3555.43,722.53 3581.32,722.53 3588.46,715.39 U30.1@3623.07,715.39
  Bottom Layer w5.3: v1(3524.33,722.69) 3613.2,722.69 R334.1@3621.06,714.83
NetD16_2: D16.2 R107.1 | length 58.2
  Top Layer w5.3: R107.1@3626.8,180.47 3626.8,124.71 D16.2@3628.5,123
NetDS1_2: DS1.2 R2.1 | length 64.8
  Top Layer w5.3: DS1.2@4.52,1641.17 18.93,1626.75 R2.1@63.34,1626.75
NetDS2_1: DS2.1 Q1.2 | length 58.9
  Top Layer w5.3: DS2.1@2647.24,963.13 2650.21,960.16 Q1.2@2704.93,960.16
NetDS2_2: DS2.2 R79.1 | length 52.1
  Top Layer w5.3: DS2.2@2647.24,1026.12 R79.1@2647.24,1078.27
NetDS3_1: DS3.1 Q2.3 | length 65.4
  Top Layer w5.3: DS3.1@2824.74,1260.6 2825.35,1259.99 Q2.3@2889.89,1259.99
NetDS3_2: DS3.2 R83.1 | length 61.3
  Top Layer w5.3: R83.1@2763.68,1198.21 2764.28,1197.6 DS3.2@2824.74,1197.6
NetL4_1: L4.1 U28.15 | length 70.2
  Top Layer w10: 3319.74,253.24 3336.27,269.76 U28.15@3336.27,316.58
NetL5_1: L5.1 U28.17 | length 61.6
  Top Layer w10: U28.17@3375.64,316.58 3375.64,276.22 3390.62,261.24
NetQ1_1: Q1.1 R82.2 | length 50.4
  Top Layer w5.3: Q1.1@2704.93,1011.34 2704.93,1061.16 R82.2@2705.34,1061.57
NetQ2_1: Q2.1 R86.2 | length 50.3
  Top Layer w5.3: Q2.1@2964.69,1234.4 Q2.1@2964.69,1234.4 R86.2@3014.94,1234.45
NetQ3_1: Q3.1 R325.2 | length 1036.6
  Top Layer w5.3: v1(2999.63,1123.11) 3029.14,1093.6 Q3.1@3029.14,1062.88
  SIG 1 w4.75: v1(2999.63,1123.11) 2999.63,1126.12 3058.74,1185.23 3257.26,1185.23 3273.43,1185.23 3517.23,1185.23 3573.12,1241.12 3573.12,1252.51 v1(3574.07,1253.47)
  Bottom Layer w5.3: v1(3574.07,1253.47) 3638.88,1253.47 3703.38,1188.97 3848.97,1188.97 3853.76,1184.18 R325.2@3853.76,1165.28
NetR32_1: R32.1 U9.10 | length 96.4
  Top Layer w5.3: U9.10@1484.79,1387.95 R32.1@1581.16,1387.95
NetR33_1: R33.1 U9.11 | length 96.4
  Top Layer w5.3: U9.11@1484.79,1437.95 R33.1@1581.16,1437.95
NetR34_1: R34.1 U9.12 | length 96.4
  Top Layer w5.3: U9.12@1484.79,1487.95 R34.1@1581.16,1487.95
NetR35_1: R35.1 U9.13 | length 96.4
  Top Layer w5.3: U9.13@1484.79,1537.95 R35.1@1581.16,1537.95
NetR36_1: R36.1 U9.14 | length 96.4
  Top Layer w5.3: U9.14@1484.79,1587.95 R36.1@1581.16,1587.95
NetR37_1: R37.1 U9.15 | length 96.4
  Top Layer w5.3: U9.15@1484.79,1637.95 R37.1@1581.16,1637.95
NetR59_1: R59.1 R60.2 U20.2 | length 119.7
  Top Layer w10: U20.2@2172.49,510.44 2185.14,510.44 2196.06,521.35 R59.1@2226.62,521.35 2226.62,581.29 R60.2@2227.39,582.06
NetR61_1: R61.1 R365.2 U60.1 | length 155.5
  Top Layer w5.3: R61.1@2284.18,1170.68 v1(2313.09,1170.68)
  Bottom Layer w5.3: U60.1@2278.46,1229.7 2307.85,1229.7 2315.3,1222.25 2315.3,1170.68 R365.2@2280.24,1170.68
NetR64_1: R64.1 U23.3 | length 58.9
  Top Layer w5.3: R64.1@2395.51,686.11 2401.27,691.87 2412.04,691.87 2430.4,710.23 2441.5,710.23 U23.3@2443.57,712.31
NetR65_1: R65.1 U23.2 | length 54.1
  Top Layer w5.3: R65.1@2396.51,717.8 2398.48,717.8 2405.67,725 2405.67,726.97 2410.7,731.99 U23.2@2443.57,731.99
NetR68_2: R68.2 SW4.1 | length 84.4
  Top Layer w12: SW4.1@2402.94,936.88 R68.2@2487.31,936.88
NetR69_2: R69.2 SW4.2 | length 84.4
  Top Layer w12: SW4.2@2402.94,986.88 R69.2@2487.31,986.88
NetR70_2: R70.2 SW4.3 | length 84.4
  Top Layer w12: SW4.3@2402.94,1036.88 R70.2@2487.31,1036.88
NetR71_2: R71.2 SW4.4 | length 84.4
  Top Layer w12: SW4.4@2402.94,1086.88 R71.2@2487.31,1086.88
NetR94_1: R94.1 U28.7 | length 68.4
  Top Layer w5.3: R94.1@3283.35,506.89 3281.07,504.61 3281.07,469.22 3296.9,453.39 U28.7@3296.9,446.01
NetR108_2: R108.2 U34.K2 | length 342.3
  Top Layer w3.94: 4043.66,1054.49 4107.28,1054.49 U34.K2@4120.08,1067.29
  Top Layer w5.3: R108.2@3797.22,1020.3 3835.49,1020.3 3844.19,1029 3973.85,1029 3999.34,1054.49 4043.66,1054.49
NetR109_2: R109.2 U34.L2 | length 349.2
  Top Layer w3.94: 4043.66,1028.9 4107.28,1028.9 U34.L2@4120.08,1041.7
  Top Layer w5.3: R109.2@3798.76,979.21 3801.14,976.83 3820.84,976.83 3835.47,976.83 3844.48,985.83 3962.08,985.83 4005.15,1028.9 4043.66,1028.9
NetR110_2: R110.2 U34.P1 | length 332.1
  Top Layer w5.3: R110.2@3800.09,881.27 3821.45,881.27 3825.18,877.54 3954.1,877.54 4041.49,964.93 U34.P1@4094.49,964.93
NetR114_2: R114.2 U34.N1 | length 326.8
  Top Layer w5.3: R114.2@3800.21,916.94 3805.94,922.66 3838.79,922.66 3841.27,920.18 3918.57,920.18 3933.23,934.84 3966.63,934.84 4022.3,990.52 U34.N1@4094.49,990.52
NetR119_2: R119.2 U34.R1 | length 339.3
  Top Layer w5.3: R119.2@3800.79,839.37 3805.79,834.36 3940.9,834.36 3964.14,857.6 4000.88,894.34 4045.88,939.34 4079.62,939.34 U34.R1@4094.49,939.34
NetR121_2: R121.2 R333.2 U30.4 | length 104.5
  Top Layer w5.3: U30.4@3711.65,664.21 v1(3743.34,664.21) 3754.36,653.2 R121.2@3776.98,653.2
  Bottom Layer w5.3: R333.2@3711.65,671.25 3736.3,671.25 v1(3743.34,664.21)
NetR122_2: R122.2 U34.K1 | length 212.9
  Top Layer w5.3: R122.2@3894.34,1050.05 3916.37,1050.05 3923.19,1043.23 3970.77,1043.23 3994.83,1067.29 U34.K1@4094.49,1067.29
NetR125_2: R125.2 U34.P2 | length 265.1
  Top Layer w3.94: 4043.69,952.13 4107.28,952.13 U34.P2@4120.08,964.93
  Top Layer w5.3: R125.2@3899.85,856.62 3948.17,856.62 4043.66,952.1
NetR126_2: R126.2 U34.M2 | length 252.1
  Top Layer w3.94: 4043.66,1003.31 4107.28,1003.31 U34.M2@4120.08,1016.11
  Top Layer w5.3: R126.2@3899.71,939.43 3905.42,945.14 3962.36,945.14 4020.53,1003.31 4043.66,1003.31
NetR128_2: R128.2 U34.R2 | length 272.6
  Top Layer w3.94: 4043.66,920.27 4049.93,926.54 4107.28,926.54 U34.R2@4120.08,939.34
  Top Layer w5.3: R128.2@3900.57,811.26 3934.64,811.26 4043.66,920.27
NetR129_2: R129.2 U34.N2 | length 260.4
  Top Layer w3.94: 4043.66,977.72 4107.28,977.72 U34.N2@4120.08,990.52
  Top Layer w5.3: R129.2@3900.38,899.94 3904.25,896.07 3953.99,896.07 3957.64,896.07 3969.08,907.51 4039.3,977.72 4043.66,977.72
NetR130_2: R130.2 U34.L1 | length 208
  Top Layer w5.3: R130.2@3900.72,1007.37 3967.65,1007.37 4001.98,1041.7 U34.L1@4094.49,1041.7
NetR133_2: R133.2 U34.A5 | length 151.6
  Top Layer w5.3: R133.2@4140.57,1425.86 4140.57,1405.8 4196.85,1349.53 U34.A5@4196.85,1297.6
NetR135_2: R135.2 U34.A6 | length 145.2
  Top Layer w5.3: R135.2@4190.71,1429.66 4190.71,1388.46 4222.44,1356.73 4222.44,1313.55 U34.A6@4222.44,1297.6
NetR137_2: R137.2 U34.B7 | length 179.5
  Top Layer w3.94: U34.B7@4248.03,1272.01 4260.82,1284.81 4260.82,1325.16
  Top Layer w5.3: R137.2@4231.93,1434.26 4231.93,1425.91 4260.81,1397.02 4260.81,1325.18
NetR138_2: R138.2 U34.B8 | length 200.2
  Top Layer w3.94: U34.B8@4273.62,1272.01 4286.41,1284.81 4286.41,1325.16
  Top Layer w5.3: R138.2@4269.11,1459.71 4269.11,1444.68 4284.61,1429.18 4284.61,1371.98 4286.41,1370.17 4286.41,1325.17
NetR141_2: R141.2 U34.A10 | length 146.3
  Top Layer w5.3: U34.A10@4324.8,1297.6 4324.8,1388.49 4321.64,1391.66 4321.64,1436.55 R141.2@4325.9,1440.81
NetR144_2: R144.2 U34.B11 | length 218.7
  Top Layer w3.94: U34.B11@4350.39,1272.01 4363.19,1284.81 4363.19,1322.21
  Top Layer w5.3: 4363.19,1322.21 4363.19,1349.27 4382.87,1368.95 4382.87,1437.61 4398.73,1453.47 4400.7,1453.47 4407.89,1460.66 R144.2@4407.89,1462.63 ; R144.2@4410.19,1460.34 R144.2@4412.38,1462.54
NetR145_2: R145.2 U34.B12 | length 202.9
  Top Layer w3.94: U34.B12@4375.98,1272.01 4388.9,1284.94 4388.9,1292.18 4388.78,1292.3 4388.78,1302.9 4388.82,1302.95 4388.82,1315.32
  Top Layer w5.3: 4388.82,1315.32 4388.82,1344.93 4450.05,1406.15 R145.2@4450.05,1444.12
NetR148_2: R148.2 U34.A13 | length 206.7
  Top Layer w5.3: U34.A13@4401.57,1297.6 4401.57,1342.68 4502.07,1443.18 R148.2@4502.07,1462.63
NetR162_2: R162.2 U34.Y19 | length 404.6
  Top Layer w5.3: U34.Y19@4555.12,811.38 4578.88,787.62 4693.51,787.62 4751.13,730 4808.09,730 4826.91,711.18 4869.86,711.18 4875.99,705.05 R162.2@4915.68,705.05
NetR164_2: R164.2 U34.V20 | length 364.8
  Top Layer w5.3: U34.V20@4580.71,862.57 4596.56,862.57 4624.25,862.57 4757.09,862.57 4823.33,796.32 4830.8,796.32 4831.02,796.1 4846.47,796.1 4846.68,796.32 R164.2@4917.85,796.32
NetR165_2: R165.2 U34.U20 | length 359.1
  Top Layer w5.3: U34.U20@4580.71,888.16 4810.82,888.16 4815.18,883.79 4859.05,839.92 R165.2@4919.79,839.92
NetR166_2: R166.2 U34.T19 | length 383.5
  Top Layer w3.94: U34.T19@4555.12,913.75 4567.91,926.54 4575.41,926.54 4621.75,926.54
  Top Layer w5.3: 4621.75,926.54 4624.25,929.04 4724.96,929.04 4732.04,921.96 4830.95,921.96 4854.62,898.29 R166.2@4919.55,898.29
NetR167_2: R167.2 U34.R19 | length 390.7
  Top Layer w3.94: U34.R19@4555.12,939.34 4567.91,952.13 4624.25,952.13
  Top Layer w5.3: 4624.25,952.13 4634.85,952.13 4634.98,952 4701.41,952 4723.21,973.8 4820.35,973.8 4821.69,972.47 4829.2,964.95 4837.26,956.89 4837.54,956.89 4842.23,952.2 4842.37,952.2 4853.51,941.07 R167.2@4917.85,941.07
NetR168_2: R168.2 U34.Y18 | length 457
  Top Layer w5.3: U34.Y18@4529.52,811.38 4529.52,799.48 4567.85,761.15 4681.54,761.15 4744.38,698.31 4796.59,698.31 4814.76,680.14 4850,680.14 4867.72,662.42 R168.2@4917.85,662.42
NetR169_2: R169.2 U34.W20 | length 376
  Top Layer w5.3: U34.W20@4580.71,836.97 4747.69,836.97 4835.88,748.79 R169.2@4920.18,748.79
NetR176_2: R176.2 U34.W19 | length 508.4
  Top Layer w3.94: U34.W19@4555.12,836.97 4567.91,824.18 4624.25,824.18
  Top Layer w5.3: 4624.25,824.18 4678.23,824.18 4754.41,748 4806.59,748 4827.65,726.94 R176.2@5017.96,726.94
NetR177_2: R177.2 U34.V18 | length 529.2
  Top Layer w3.94: U34.V18@4529.52,862.57 4542.32,849.77 4624.25,849.77
  Top Layer w5.3: 4624.25,849.77 4646.76,849.77 4646.85,849.86 4751.28,849.86 4831.14,770 R177.2@5020.31,770
NetR178_2: R178.2 U34.V19 | length 494.1
  Top Layer w3.94: U34.V19@4555.12,862.57 4567.91,875.36 4575.41,875.36 4586.01,875.36 4586.09,875.27 4624.25,875.27
  Top Layer w5.3: 4624.25,875.27 4805.61,875.27 4807.15,873.81 4863.76,819.85 4867.42,818.39 5018.35,818.39 R178.2@5020.48,816.26
NetR179_2: R179.2 U34.T20 | length 456.4
  Top Layer w5.3: U34.T20@4580.71,913.75 4624.25,913.75 4628.25,913.75 4630.34,911.66 4819.91,911.66 4826.59,904.99 4855.62,875.96 5018.08,875.96 R179.2@5020.48,878.37
NetR180_2: R180.2 U34.R20 | length 468.3
  Top Layer w5.3: U34.R20@4580.71,939.34 4596.56,939.34 4624.25,939.34 4705.64,939.34 4728.14,961.83 4816.08,963.5 4859.69,919.9 5017.68,919.9 R180.2@5020.48,922.71
NetR182_2: R182.2 U34.W18 | length 566
  Top Layer w3.94: U34.W18@4529.52,836.97 4542.32,824.18 4542.32,804.68 4567,780
  Top Layer w5.3: 4567,780 4570.93,776.07 4686.95,776.07 4749.02,714 4803.21,714 4821.27,695.93 4855.39,695.93 4867.3,684.02 R182.2@5020.79,684.02
NetR251_2: R251.2 U52.1 | length 77.9
  Bottom Layer w5.3: U52.1@6168.23,296.1 6186.29,296.1 6195.31,305.12 6195.31,322.71 6205.31,332.71 R251.2@6220.63,332.71
NetR252_2: R252.2 U52.4 | length 60.7
  Bottom Layer w5.3: U52.4@6168.23,219.33 6187.98,219.33 6205.63,201.68 R252.2@6205.63,185.71
NetR310_2: R310.2 U34.T18 | length 47.2
  Top Layer w5.3: v1(4526.19,898.04) 4529.52,901.37 U34.T18@4529.52,913.75
  Bottom Layer w5.3: v1(4526.19,898.04) 4526.84,897.39 R310.2@4556.06,897.39
NetR311_2: R311.2 U34.R17 | length 51.3
  Top Layer w5.3: U34.R17@4504.03,939.43 4520.4,939.43 v1(4523.49,936.34)
  Bottom Layer w5.3: v1(4523.49,936.34) 4524.28,937.13 R311.2@4553.7,937.13
NetR317_2: R317.2 U34.C12 | length 220.6
  Top Layer w5.3: v1(4364.52,1254.55) 4367.86,1254.55 U34.C12@4375.98,1246.42
  Bottom Layer w5.3: R317.2@4325.9,1440.81 4321.64,1436.55 4321.64,1334.64 4364.52,1291.75 v1(4364.52,1254.55)
NetR324_2: R324.2 U34.R4 | length 293.9
  Top Layer w5.3: U34.R4@4171.26,939.34 4172.88,940.96 4172.88,947.77 4176,950.89 v1(4176,954.32)
  Bottom Layer w3.94: 4043.66,939.35 4110.51,939.35 4135.85,964.69 4165.09,964.69 v1@4175.46,954.32
  Bottom Layer w4: v1@4175.46,954.32 v1(4176,954.32)
  Bottom Layer w5.3: R324.2@3938.33,880.3 3978.1,880.3 4037.15,939.35 4043.66,939.35
NetR329_2: R329.2 U34.L4 | length 395
  Top Layer w5.3: v1(4142.26,1045.03) 4145.59,1041.7 U34.L4@4171.26,1041.7
  Bottom Layer w5.3: R329.2@3800.21,1060.1 3901.65,1060.1 3929.12,1032.63 3996.65,1032.63 3999.49,1035.47 4016.32,1052.3 4134.99,1052.3 v1(4142.26,1045.03)
NetR330_2: R330.2 U34.J3 | length 435.4
  Top Layer w5.3: v1(4138.57,1106.76) 4138.57,1099.98 U34.J3@4145.67,1092.88
  Bottom Layer w5.3: R330.2@3798.16,1138.22 3903.39,1138.22 3929.73,1111.88 3929.73,1069.84 3941.75,1057.81 3991.85,1057.81 4026.92,1092.88 4124.69,1092.88 v1(4138.57,1106.76)
NetR331_2: R331.2 U34.K4 | length 403.5
  Top Layer w3.94: v1(4150,1070.91) 4153.79,1070.91 4167.63,1070.91 U34.K4@4171.26,1067.29
  Bottom Layer w5.3: R331.2@3799.18,1092.98 3823.88,1092.98 3846.39,1070.47 3908.46,1070.47 3933.16,1045.77 3995.23,1045.77 4020.37,1070.91 v1(4150,1070.91)
NetR332_2: R332.2 U34.M3 | length 393.2
  Top Layer w5.3: U34.M3@4145.67,1016.11 4145.76,1016.02 4145.76,1001.56 v1(4145.85,1001.47)
  Bottom Layer w5.3: R332.2@3800.09,1020.43 3800.89,1019.63 3998.64,1019.63 4020.17,1041.16 4118.17,1041.16 4145.17,1014.17 4145.17,1002.15 v1(4145.85,1001.47)
NetR346_1: R346.1 U28.10 | length 72
  Top Layer w5.3: v1(3250.34,381.29) 3250.59,381.54 U28.10@3290.99,381.54
  Bottom Layer w10: R346.1@3240.34,408.41 3240.34,391.29 v1(3250.34,381.29)
NetR351_2: R351.2 R353.2 U58.4 | length 107.5
  Bottom Layer w5.3: R353.2@2821.99,666.4 2825.92,662.46 R351.2@2870.22,662.46 2870.04,662.28 U58.4@2870.04,604.91
NetR357_2: R357.2 U59.7 | length 43.8
  Bottom Layer w5.3: R357.2@2568.57,584.08 U59.7@2612.32,584.08
NetR366_2: R366.2 U61.4 U61.5 | length 145.4
  Bottom Layer w5.3: R366.2@2177.69,927.14 2177.38,927.46 2177.38,976.16 2182.75,981.53 U61.5@2209.76,981.53 2209.76,963.68 2218.86,954.58 2228.79,954.58 2233.38,959.17 U61.4@2233.38,973.66
NetR380_1: R380.1 U12.7 | length 89.4
  Top Layer w5.3: v1(1137.37,732.59) 1137.81,733.03 U12.7@1193.7,733.03
  Bottom Layer w5.3: v1(1137.37,732.59) 1137.81,733.03 R380.1@1170.08,733.03
NetR381_1: R381.1 U12.6 | length 94.8
  Top Layer w5.3: v1(1134.47,783.03) U12.6@1193.7,783.03
  Bottom Layer w5.3: v1(1134.47,783.03) R381.1@1170.08,783.03
NetR400_1: R400.1 U7.7 | length 93.3
  Top Layer w5.3: U7.7@827.09,1849.31 827.09,1907.56 v1(827.25,1907.72)
  Bottom Layer w5.3: R400.1@827.09,1872.94 827.09,1907.56 v1(827.25,1907.72)
NetR405_1: R405.1 U5.6 | length 98.1
  Top Layer w5.3: U5.6@591.82,1847.11 v1(591.82,1907.98)
  Bottom Layer w5.3: R405.1@591.82,1870.74 v1(591.82,1907.98)
NetR407_1: R407.1 U5.7 | length 98.1
  Top Layer w5.3: U5.7@541.82,1847.11 v1(541.82,1907.98)
  Bottom Layer w5.3: R407.1@541.82,1870.74 v1(541.82,1907.98)
NetTP9_1: TP9.1 U63.75 | length 131.5
  Top Layer w5.3: v1(888.6,1260.98) 921.09,1260.98 TP9.1@948.65,1288.54
  Bottom Layer w5.3: v1(888.6,1260.98) U63.75@948.65,1260.98
NetU39_2: U39.2 U55.4 | length 77.9
  Top Layer w5.3: v1(4934.62,1565.65) 4946.61,1577.64 U39.2@4968.56,1577.64
  Bottom Layer w5.3: v1(4934.62,1565.65) 4934.62,1564.25 4943.76,1555.11 U55.4@4943.76,1530.43
OSC1_CLK_OUT: R211.1 Y2.3 | length 57.7
  Top Layer w5.3: Y2.3@6650.85,332.64 6651.09,332.4 R211.1@6651.09,275.05
OSC2_CLK_OUT: R214.1 Y3.3 | length 62.1
  Top Layer w5.3: Y3.3@6610.65,1674.86 6610.94,1675.15 R214.1@6610.94,1736.89
OSC_CLK_OUT1: J21.28 R211.2 R212.2 TP47.1 | length 281.1
  Top Layer w5.3: TP47.1@6553.85,225.77 6553.85,265.12 6563.78,275.05 R211.2@6603.84,275.05 ; J21.28@6593.79,91.39 6593.79,141.03 6604.07,151.32 6604.07,205.39 R211.2@6604.07,274.82
OSC_CLK_OUT2: J23.28 R213.2 R214.2 TP53.1 | length 247.1
  Top Layer w5.3: J23.28@6668.69,1908.44 6668.69,1826 6668.69,1823.55 6657.82,1812.69 R213.2@6657.82,1790.07 6657.82,1737.25 R214.2@6658.18,1736.89 6697.68,1736.89 TP53.1@6719.86,1759.06
OSPI0_D0: R100.2 U26.D3 | length 205.4
  Top Layer w5.3: U26.D3@3333.26,1025.23 3352.22,1006.27 3352.22,959.73 3437.28,874.66 3437.28,867.23 3440.15,864.37 R100.2@3440.45,864.37
OSPI0_D1: R97.2 U26.D2 | length 175.9
  Top Layer w5.3: U26.D2@3293.89,1025.23 3314.46,1004.66 3314.46,909.64 3330.3,893.79 R97.2@3330.3,864.37
OSPI0_D2: R103.2 U26.C4 | length 171.6
  Top Layer w5.3: U26.C4@3372.63,1064.6 3392.95,1044.28 3449.31,1044.28 3467.09,1062.05 3467.09,1089.99 3482.55,1105.45 R103.2@3494.09,1105.45
OSPI0_D3: R104.2 U26.D4 | length 134.2
  Top Layer w5.3: U26.D4@3372.63,1025.23 3391.77,1006.08 3465.62,1006.08 3477.33,1017.79 R104.2@3494.09,1017.79
OSPI0_D4: R105.2 U26.D5 | length 96.8
  Top Layer w5.3: U26.D5@3412,1025.23 3448.82,1025.23 3484.38,1060.79 R105.2@3494.09,1060.79
OSPI0_D5: R98.2 U26.E3 | length 142.9
  Top Layer w5.3: U26.E3@3333.26,985.86 3333.26,934.35 3384.85,882.77 R98.2@3384.85,864.37
OSPI0_D6: R95.2 U26.E2 | length 129.5
  Top Layer w5.3: R95.2@3274.55,864.37 3274.55,890.95 3293.89,910.29 U26.E2@3293.89,985.86
OSPI0_D7: R92.2 U26.E1 | length 135.9
  Top Layer w5.3: R92.2@3219.74,864.37 3219.74,875.51 3254.52,910.29 U26.E1@3254.52,985.86
OSPI0_RESET_OUT0: R344.1 U25.13 U27.1 | length 632.4
  Top Layer w5.3: U25.13@3048.18,1614.03 3048.18,1632.13 3072.06,1656 v1(3089,1656) ; v1(3219.47,1448.31) 3219.47,1349.12 3229.85,1338.74 U27.1@3265.34,1338.74
  SIG 1 w5.3: v1(3089,1656) 3089,1626.29 3193.11,1522.19 3193.11,1474.67 v1(3219.47,1448.31)
  Bottom Layer w5.3: v1(3219.47,1448.31) 3219.47,1349.12 3229.65,1338.94 3267.59,1338.94 R344.1@3268.27,1338.26
OSPI0_RSTn: R99.1 U26.A4 U27.4 | length 206.9
  Top Layer w5.3: U26.A4@3372.63,1143.34 3372.63,1183.71 3423.46,1234.54 R99.1@3423.46,1274.81 3406.78,1274.81 3395.91,1263.93 U27.4@3373.61,1263.93
OSPI1_CLK: R242.2 R250.1 R253.2 TP44.1 U51.B2 | length 431.1
  Top Layer w5.3: TP44.1@6235.8,826.4 6264.42,826.4 v1(6265.78,825.03)
  Bottom Layer w5.3: U51.B2@6082.37,844.97 6101.89,825.45 6101.89,770.37 6109.36,762.9 6128.12,762.9 6189.49,824.27 R253.2@6235.99,824.27 v1@6265.78,824.27 ; v1(6265.78,825.03) 6289.39,825.03 R250.1@6290.18,824.24 6328.32,824.24 6344.05,839.97 R242.2@6344.05,880.32
OSPI1_CSN0: R248.2 R255.2 TP41.1 U51.C2 | length 606.9
  Top Layer w5.3: TP41.1@6050.85,744.69 6070.62,744.69 v1(6080.43,754.51)
  SIG 1 w4.75: v1(6080.43,754.51) 6120.63,754.51 6321.24,955.12 v1(6321.24,968.9)
  Bottom Layer w5.3: U51.C2@6043,844.97 6023.05,825.03 6023.05,766.61 6037.35,752.31 R255.2@6037.35,715.03 6056.54,715.03 6080.43,738.92 v1(6080.43,754.51) ; v1(6321.24,968.9) 6322.26,967.89 R248.2@6343.71,967.89
OSPI1_D0: R269.2 U51.D3 | length 213
  Bottom Layer w5.3: R269.2@5824.89,967 5854.5,967 5918.81,902.68 5985.29,902.68 U51.D3@6003.63,884.34
OSPI1_D0_R: R197.2 R269.1 R291.2 TP37.1 | length 1307.2
  Top Layer w5.3: TP37.1@5731.56,968.63 5759.29,968.63 v1(5760.91,967) R197.2@5791.23,967
  SIG 1 w4.75: v1(5560.85,598.43) 5560.85,537.15 5626,472 5756.96,472 6023.42,738.47 6023.42,938.61 5962.04,1000 5793.92,1000 v1(5760.91,967)
  Bottom Layer w5.3: R291.2@5521.14,598.74 5560.85,598.74 v1(5560.85,598.43) ; v1(5760.91,967) R269.1@5804.81,967
OSPI1_D1: R263.2 U51.D2 | length 167
  Bottom Layer w5.3: R263.2@5982.95,692.44 5982.47,692.92 5982.47,755.38 5975.86,761.99 5975.86,789.93 5985.33,799.4 5985.33,826.68 U51.D2@6003.63,844.97
OSPI1_D1_R: R203.2 R263.1 R282.2 TP40.1 | length 1285.5
  Top Layer w5.3: R203.2@5982.95,658.78 5991.41,667.24 v1(6004.36,667.24) 6007.8,667.24 6022.96,682.4 TP40.1@6027.61,682.4
  SIG 1 w5.3: v1(5651.69,663.42) 5575,663.42 5521.14,609.56 5521.14,521.86 5591.33,451.67 5829.59,451.67 5882.37,504.44 5913.64,535.72 5919.05,535.72 5924.28,530.49 5929.69,530.49 5935.1,535.9 5935.1,541.31 5915.73,560.68 5915.73,566.09 5921.13,571.5 5926.54,571.5 5949.42,548.62 5954.83,548.62 5960.24,554.03 5960.24,559.44 5937.36,582.32 5937.36,587.73 5942.77,593.13 5948.18,593.13 5971.06,570.26 5976.47,570.26 5981.88,575.67 5981.88,581.08 5959,603.95 5959,609.36 5964.41,614.77 5969.82,614.77 5992.69,591.9 5998.1,591.9 6003.51,597.31 6003.51,602.72 5980.64,625.59 5980.64,631 5986.05,636.41 5991.46,636.41 6014.33,613.53 6019.74,613.53 6025.15,618.94 6025.15,624.35 6004.36,645.14 6004.36,648.89 v1(6004.36,667.24)
  Bottom Layer w5.3: R282.2@5625.42,663.42 v1(5651.69,663.42) ; R263.1@5982.95,672.36 5984.45,670.86 5997.3,670.86 6000.93,667.24 v1(6004.36,667.24)
OSPI1_D2: R254.2 U51.C4 | length 166.2
  Bottom Layer w5.3: U51.C4@6043,923.71 6062.81,943.52 6062.81,978.86 6039.85,1001.82 6039.85,1025.28 6058.96,1044.38 R254.2@6058.96,1064.27
OSPI1_D2_R: R205.1 R254.1 R294.2 TP42.1 | length 1426.9
  Top Layer w5.3: v1(6034.98,1082.39) 6050.52,1097.93 R205.1@6058.96,1097.93 TP42.1@6058.96,1145.32
  SIG 1 w4.75: v1(5547.45,697.5) 5547.45,759.81 5442.07,865.19 5442.07,1007.43 5442.61,1007.97 5442.61,1057.97 5568.63,1184 5958.36,1184 5983.72,1209.37 5988.94,1209.37 5994.15,1204.15 5994.15,1198.94 5971.09,1175.87 5971.09,1170.65 5976.3,1165.44 5981.52,1165.44 6004.58,1188.51 6009.8,1188.51 6015.01,1183.29 6015.01,1178.08 5991.94,1155.01 5991.94,1149.79 5997.16,1144.58 6002.37,1144.58 6021.29,1163.49 6026.5,1163.49 6031.72,1158.27 6031.72,1153.06 6026.95,1148.29 6026.95,1143.07 6033.32,1136.7 6034.98,1135.04 v1(6034.98,1082.39)
  Bottom Layer w5.3: R294.2@5520.97,697.28 5547.24,697.28 v1(5547.45,697.5) ; v1(6034.98,1082.39) 6036.94,1084.35 R254.1@6058.96,1084.35
OSPI1_D3: R270.2 U51.D4 | length 217
  Bottom Layer w5.3: R270.2@5824.7,1015.72 5849.56,1015.72 5922.9,942.39 5984.95,942.39 U51.D4@6003.63,923.71
OSPI1_D3_R: R196.2 R270.1 R283.2 TP38.1 | length 1232.3
  Top Layer w5.3: TP38.1@5732.87,1016.46 5761.2,1016.46 v1(5761.93,1015.72) ; v1@5763.98,1015.72 R196.2@5791.04,1015.72
  SIG 1 w4.75: v1(5647.75,766.53) 5647.75,733.4 5639.41,725.06 5584.14,725.06 5576.59,732.61 5576.59,753.78 5580.28,757.47 5612.91,757.47 5616.59,761.15 5616.59,768.53 5612.91,772.22 5600.28,772.22 5596.59,775.9 5596.59,802.65 5519.22,880.02 5519.22,910.02 5495.68,933.56 5495.68,1052.68 5541,1098 5716.92,1098 5732.9,1082.02 5836.43,1082.02 5843,1075.45 5843,1068.08 5839.31,1064.39 5766.69,1064.39 5763,1060.7 5763,1053.33 5766.69,1049.64 5799.31,1049.64 5803,1045.95 5803,1024.34 5794.39,1015.72 v1(5761.93,1015.72)
  Bottom Layer w5.3: R283.2@5621.27,766.32 5647.54,766.32 v1(5647.75,766.53) ; v1(5761.93,1015.72) R270.1@5804.62,1015.72
OSPI1_D4: R256.2 U51.D5 | length 101.2
  Bottom Layer w5.3: U51.D5@6003.63,963.08 R256.2@6003.63,1064.27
